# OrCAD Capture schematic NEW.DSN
size A
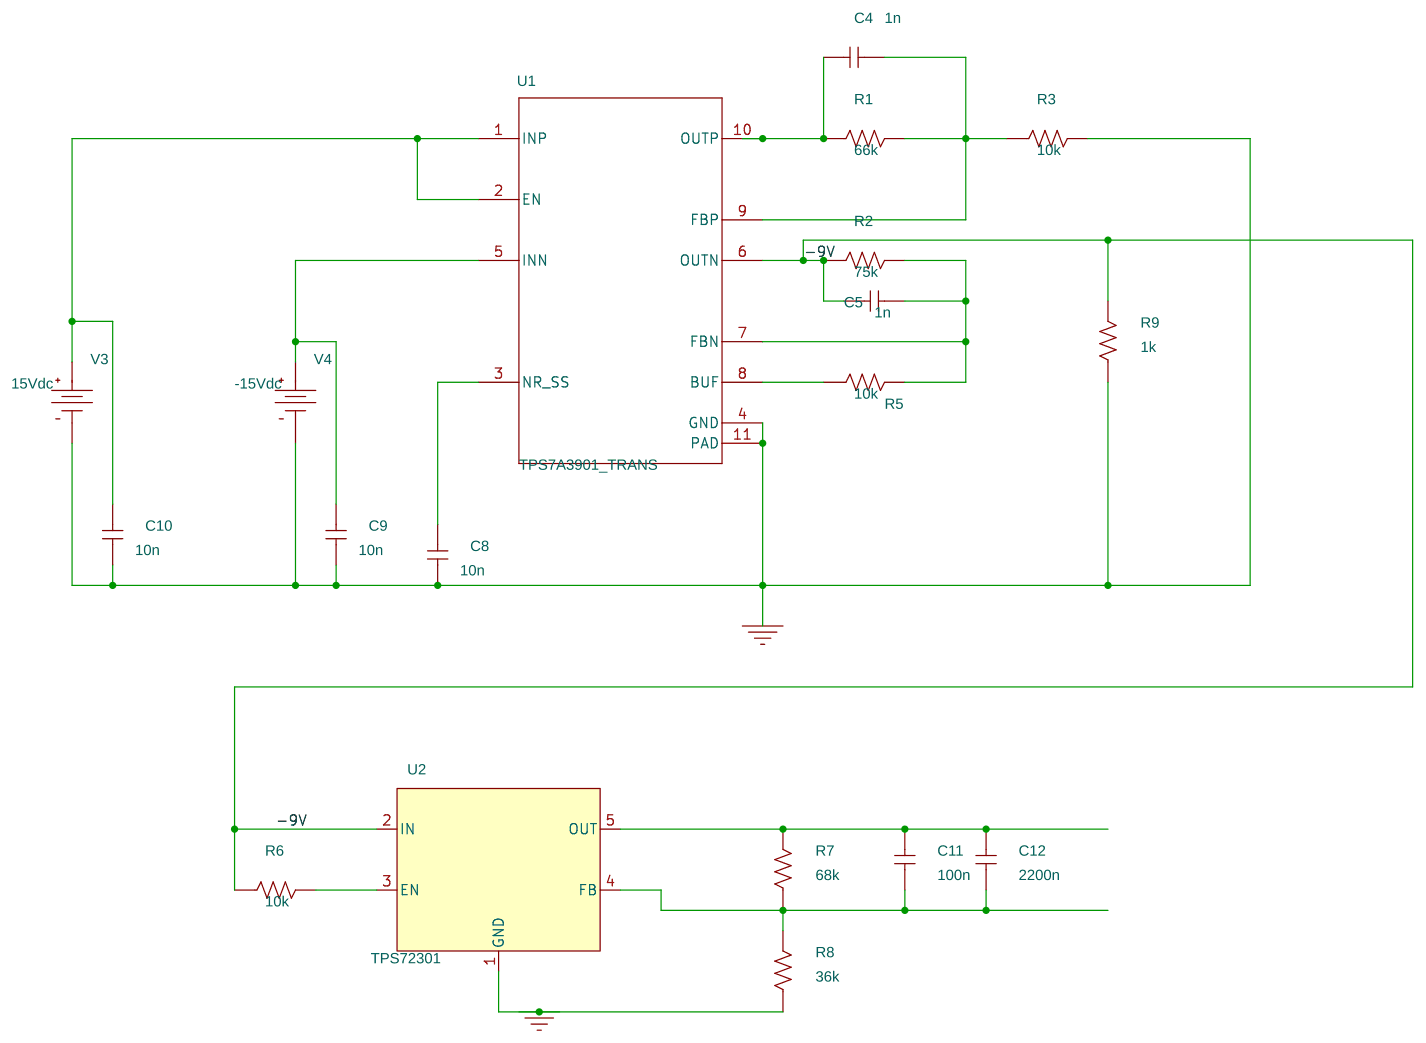
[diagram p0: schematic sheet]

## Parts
C4  1n  [cap196]
C5  1n  [cap196]
C8  10n  [RAD/CK05]
C9  10n  [RAD/CK05]
C10  10n  [RAD/CK05]
C11  100n  [RAD/CK05]
C12  2200n  [RAD/CK05]
R1  66k  [AXRC05]
R2  75k  [AXRC05]
R3  10k  [AXRC05]
R5  10k  [AXRC05]
R6  10k  [AXRC05]
R7  68k  [AXRC05]
R8  36k  [AXRC05]
R9  1k  [AXRC05]
U1  TPS7A3901_TRANS  [DSC0010J]
U2  TPS72301
V3  VDC
V4  VDC

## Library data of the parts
C4 C5 C8-C12 = C
R1-R3 R5-R9 = R
U1 = TPS7A3901_TRANS
U2 = TPS72301
V3 = VDC: DC: 15Vdc
V4 = VDC: DC: -15Vdc

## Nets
-9V: C5.1 R2.1 R6.1 R9.2 U1.6(OUTN) U2.2(IN)
0: C8.2 C9.2 C10.2 R3.2 R8.1 R9.1 U1.4(GND) U1.11(PAD) U2.1(GND) V3.1(-) V4.1(-)
N23634: C10.1 U1.1(INP) U1.2(EN) V3.0(+)
N23657: C9.1 U1.5(INN) V4.0(+)
N23777: C8.1 U1.3(NR_SS)
N24773: C4.1 R1.1 U1.10(OUTP)
N24782: C4.2 R1.2 R3.1 U1.9(FBP)
N24790: C5.2 R2.2 R5.2 U1.7(FBN)
N25130: R5.1 U1.8(BUF)
N26803: R6.2 U2.3(EN)
N26814: C11.2 C12.2 R7.2 U2.5(OUT)
N26818: C11.1 C12.1 R7.1 R8.2 U2.4(FB)
